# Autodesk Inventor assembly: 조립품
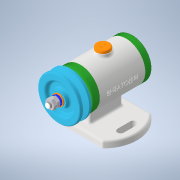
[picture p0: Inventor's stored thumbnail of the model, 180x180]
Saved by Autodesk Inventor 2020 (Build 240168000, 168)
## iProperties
Created: 2021-09
Part Number: 조립품
Document SubType Name: Assembly
Designer: Administrator
Author: Administrator
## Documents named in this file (14)
- C:\Users\Administrator\Downloads\710906V1015\조립품.iam
- C:\Users\Administrator\Downloads\710906V1015\본체.ipt
- C:\Users\Administrator\Downloads\710906V1015\축.ipt
- C:\Users\Administrator\Downloads\710906V1015\앞커버.ipt
- C:\Users\Administrator\Downloads\710906V1015\뒤커버.ipt
- C:\Users\Administrator\Downloads\710906V1015\오일 실 15x25x7.ipt
- C:\Users\Administrator\Downloads\710906V1015\베어링 15x32x9.ipt
- C:\Users\Administrator\Downloads\710906V1015\키 3x3.ipt
- C:\Users\Administrator\Downloads\710906V1015\V벨트풀리.ipt
- C:\Users\Administrator\Downloads\710906V1015\와셔 8x17.ipt
- C:\Users\Administrator\Downloads\710906V1015\스프링와셔 8.ipt
- C:\Users\Administrator\Downloads\710906V1015\너트 M8.ipt
- C:\Users\Administrator\Downloads\710906V1015\캡.ipt
- C:\Users\Administrator\Downloads\710906V1015\볼트 M4x12.ipt
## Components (1 placed, 1 different names)
1. V벨트풀리:1
